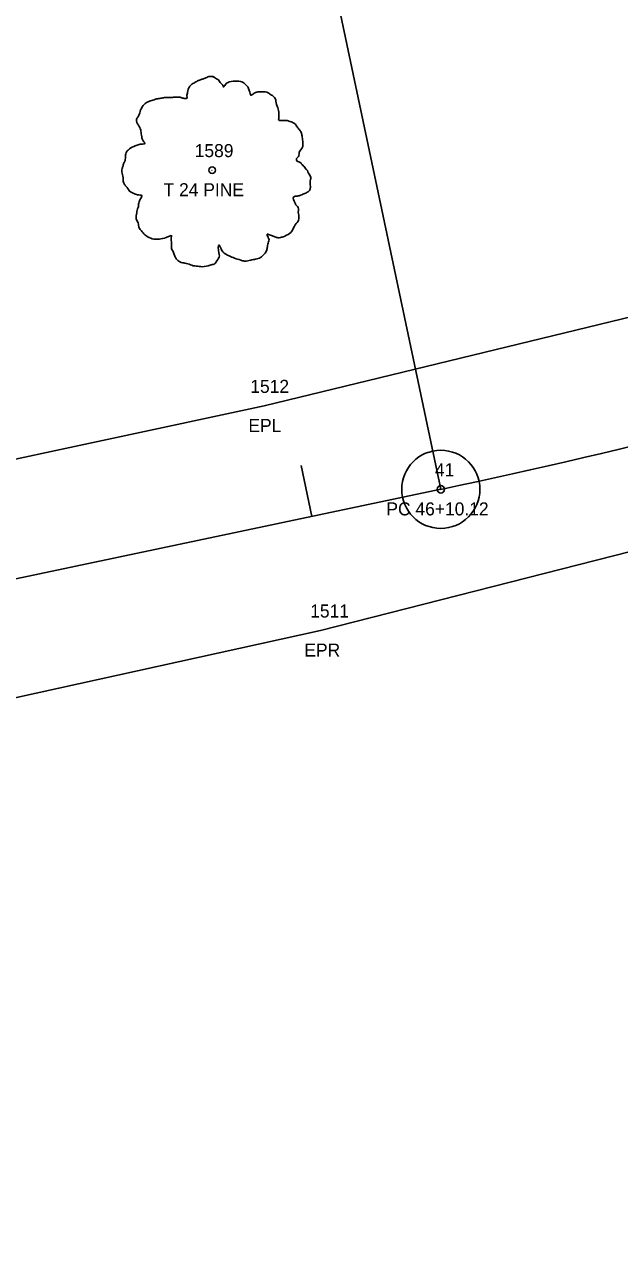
# Model space of a CAD drawing. Extents: x 1965304 to 1970247, y 1117014 to 1118201.
# Drawn here: x 1966652.9 to 1966698.6, y 1117363.8 to 1117457.6 of the extents above; entities that cross this region are included whole.
import ezdxf

# ---------------------------------------------------------------- set-up
doc = ezdxf.new("R2010")
doc.units = 0
for name, color, linetype in [('RD_EX_Road', 7, 'Continuous'), ('RD_EX_Road_txCode', 7, 'Continuous'), ('RD_EX_VEG', 7, 'Continuous'), ('RD_EX_VEG_txCode', 7, 'Continuous'), ('RD_HC_Cl', 7, 'Continuous'), ('RD_HC_Data', 7, 'Continuous'), ('RD_HC_Data_Tic', 7, 'Continuous'), ('RD_HC_txCode', 7, 'Continuous'), ('RD_SMD_Locator', 7, 'Continuous')]:
    doc.layers.add(name, color=color, linetype=linetype)

msp = doc.modelspace()

# ---------------------------------------------------------------- linework, layer by layer
at = {"layer": 'RD_EX_Road'}
for points in [[(1966031.823, 1117232.956), (1966074.66, 1117252.15), (1966117.782, 1117271.581), (1966161.06, 1117290.483), (1966205.406, 1117309.226), (1966251.249, 1117327.393), (1966297.245, 1117343.102), (1966344.085, 1117357.038), (1966390.785, 1117368.561), (1966438.122, 1117379.082), (1966484.547, 1117389.131), (1966531.199, 1117398.733), (1966578.388, 1117408.593), (1966604.527, 1117414.058), (1966624.537, 1117418.323), (1966671.319, 1117428.348), (1966716.506, 1117439.32), (1966736.604, 1117445.59), (1966754.133, 1117451.442), (1966759.658, 1117453.517), (1966769.512, 1117457.475)], [(1965729.992, 1117080.297), (1965819.77, 1117119.134), (1965907.737, 1117159.312), (1965995.365, 1117199.039), (1966039.268, 1117218.497), (1966081.241, 1117237.148), (1966124.666, 1117256.555), (1966167.659, 1117275.555), (1966211.467, 1117293.627), (1966257.791, 1117311.581), (1966302.7, 1117327.207), (1966347.903, 1117339.982), (1966394.806, 1117351.637), (1966441.557, 1117361.865), (1966488.625, 1117372.057), (1966534.906, 1117381.34), (1966581.234, 1117390.947), (1966629.533, 1117400.947), (1966675.632, 1117411.107), (1966721.676, 1117422.847), (1966766.802, 1117438.972), (1966775.751, 1117440.571)]]:
    msp.add_lwpolyline(points, dxfattribs=at)
at = {"layer": 'RD_EX_VEG'}
for centre, radius in [((1966667.339, 1117446.441), 0.25), ((1966667.339, 1117446.441), 0.25), ((1966667.326, 1117446.422), 0.0001), ((1966667.326, 1117446.422), 0.0001)]:
    msp.add_circle(centre, radius, dxfattribs=at)
for points in [[(1966667.471, 1117453.608), (1966667.171, 1117453.633), (1966666.846, 1117453.533), (1966666.596, 1117453.433), (1966666.371, 1117453.358), (1966666.146, 1117453.258), (1966665.846, 1117453.083), (1966665.622, 1117452.883), (1966665.497, 1117452.634), (1966665.447, 1117452.409), (1966665.397, 1117452.134), (1966665.397, 1117451.959), (1966665.272, 1117451.934), (1966665.122, 1117451.959), (1966664.872, 1117452.034), (1966664.622, 1117452.034), (1966664.372, 1117452.034), (1966664.022, 1117452.009), (1966663.672, 1117452.009), (1966663.398, 1117451.959), (1966663.073, 1117451.909), (1966662.698, 1117451.784), (1966662.348, 1117451.659), (1966662.048, 1117451.409), (1966661.798, 1117450.934), (1966661.673, 1117450.584), (1966661.523, 1117450.335), (1966661.673, 1117449.885), (1966661.848, 1117449.535), (1966661.873, 1117449.335), (1966661.948, 1117448.91), (1966662.048, 1117448.685), (1966662.173, 1117448.485), (1966662.098, 1117448.46), (1966661.723, 1117448.41), (1966661.423, 1117448.31), (1966660.999, 1117448.086), (1966660.774, 1117447.861), (1966660.674, 1117447.536), (1966660.649, 1117447.186), (1966660.549, 1117446.986), (1966660.474, 1117446.711), (1966660.449, 1117446.636), (1966660.399, 1117446.311), (1966660.499, 1117445.861), (1966660.524, 1117445.512), (1966660.649, 1117445.287), (1966660.799, 1117445.112), (1966660.974, 1117444.862), (1966661.373, 1117444.637), (1966661.698, 1117444.537), (1966661.898, 1117444.512), (1966661.723, 1117444.012), (1966661.673, 1117443.662), (1966661.548, 1117443.263), (1966661.548, 1117443.188), (1966661.498, 1117442.713), (1966661.648, 1117442.388), (1966661.723, 1117442.013), (1966661.898, 1117441.788), (1966662.173, 1117441.488), (1966662.498, 1117441.264), (1966662.998, 1117441.139), (1966663.398, 1117441.164), (1966663.972, 1117441.338), (1966664.222, 1117441.413), (1966664.197, 1117441.239), (1966664.222, 1117440.864), (1966664.222, 1117440.439), (1966664.372, 1117440.114), (1966664.472, 1117439.839), (1966664.622, 1117439.589), (1966664.947, 1117439.364), (1966665.347, 1117439.289), (1966665.771, 1117439.139), (1966666.221, 1117439.064), (1966666.721, 1117439.039), (1966667.321, 1117439.189), (1966667.596, 1117439.314), (1966667.696, 1117439.489), (1966667.896, 1117439.864), (1966667.846, 1117440.089), (1966667.871, 1117440.689), (1966667.97, 1117440.514), (1966668.145, 1117440.164), (1966668.645, 1117439.864), (1966669.045, 1117439.689), (1966669.52, 1117439.539), (1966669.82, 1117439.464), (1966670.294, 1117439.539), (1966670.669, 1117439.614), (1966671.044, 1117439.739), (1966671.344, 1117440.014), (1966671.519, 1117440.289), (1966671.569, 1117440.564), (1966671.644, 1117440.939), (1966671.694, 1117441.114)], [(1966667.471, 1117453.608), (1966667.171, 1117453.633), (1966666.846, 1117453.533), (1966666.596, 1117453.433), (1966666.371, 1117453.358), (1966666.146, 1117453.258), (1966665.846, 1117453.083), (1966665.622, 1117452.883), (1966665.497, 1117452.634), (1966665.447, 1117452.409), (1966665.397, 1117452.134), (1966665.397, 1117451.959), (1966665.272, 1117451.934), (1966665.122, 1117451.959), (1966664.872, 1117452.034), (1966664.622, 1117452.034), (1966664.372, 1117452.034), (1966664.022, 1117452.009), (1966663.672, 1117452.009), (1966663.398, 1117451.959), (1966663.073, 1117451.909), (1966662.698, 1117451.784), (1966662.348, 1117451.659), (1966662.048, 1117451.409), (1966661.798, 1117450.934), (1966661.673, 1117450.584), (1966661.523, 1117450.335), (1966661.673, 1117449.885), (1966661.848, 1117449.535), (1966661.873, 1117449.335), (1966661.948, 1117448.91), (1966662.048, 1117448.685), (1966662.173, 1117448.485), (1966662.098, 1117448.46), (1966661.723, 1117448.41), (1966661.423, 1117448.31), (1966660.999, 1117448.086), (1966660.774, 1117447.861), (1966660.674, 1117447.536), (1966660.649, 1117447.186), (1966660.549, 1117446.986), (1966660.474, 1117446.711), (1966660.449, 1117446.636), (1966660.399, 1117446.311), (1966660.499, 1117445.861), (1966660.524, 1117445.512), (1966660.649, 1117445.287), (1966660.799, 1117445.112), (1966660.974, 1117444.862), (1966661.373, 1117444.637), (1966661.698, 1117444.537), (1966661.898, 1117444.512), (1966661.723, 1117444.012), (1966661.673, 1117443.662), (1966661.548, 1117443.263), (1966661.548, 1117443.188), (1966661.498, 1117442.713), (1966661.648, 1117442.388), (1966661.723, 1117442.013), (1966661.898, 1117441.788), (1966662.173, 1117441.488), (1966662.498, 1117441.264), (1966662.998, 1117441.139), (1966663.398, 1117441.164), (1966663.972, 1117441.338), (1966664.222, 1117441.413), (1966664.197, 1117441.239), (1966664.222, 1117440.864), (1966664.222, 1117440.439), (1966664.372, 1117440.114), (1966664.472, 1117439.839), (1966664.622, 1117439.589), (1966664.947, 1117439.364), (1966665.347, 1117439.289), (1966665.771, 1117439.139), (1966666.221, 1117439.064), (1966666.721, 1117439.039), (1966667.321, 1117439.189), (1966667.596, 1117439.314), (1966667.696, 1117439.489), (1966667.896, 1117439.864), (1966667.846, 1117440.089), (1966667.871, 1117440.689), (1966667.97, 1117440.514), (1966668.145, 1117440.164), (1966668.645, 1117439.864), (1966669.045, 1117439.689), (1966669.52, 1117439.539), (1966669.82, 1117439.464), (1966670.294, 1117439.539), (1966670.669, 1117439.614), (1966671.044, 1117439.739), (1966671.344, 1117440.014), (1966671.519, 1117440.289), (1966671.569, 1117440.564), (1966671.644, 1117440.939), (1966671.694, 1117441.114)], [(1966671.694, 1117441.114), (1966671.619, 1117441.289), (1966671.569, 1117441.538), (1966671.644, 1117441.513), (1966671.819, 1117441.463), (1966672.094, 1117441.338), (1966672.319, 1117441.264), (1966672.643, 1117441.289), (1966672.918, 1117441.388), (1966673.368, 1117441.663), (1966673.643, 1117442.138), (1966673.918, 1117442.538), (1966673.993, 1117442.863), (1966673.943, 1117443.088), (1966673.918, 1117443.587), (1966673.718, 1117443.837), (1966673.668, 1117443.962), (1966673.568, 1117444.362), (1966673.643, 1117444.412), (1966673.918, 1117444.462), (1966674.293, 1117444.587), (1966674.568, 1117444.712), (1966674.793, 1117444.887), (1966674.867, 1117445.112), (1966674.843, 1117445.512), (1966674.892, 1117445.911), (1966674.818, 1117446.061), (1966674.718, 1117446.211), (1966674.643, 1117446.411), (1966674.493, 1117446.561), (1966674.393, 1117446.711), (1966674.293, 1117446.811), (1966674.168, 1117446.961), (1966673.993, 1117447.086), (1966673.843, 1117447.136), (1966673.793, 1117447.286), (1966673.943, 1117447.486), (1966673.993, 1117447.586), (1966674.018, 1117447.811), (1966674.243, 1117448.16), (1966674.293, 1117448.56), (1966674.243, 1117448.985), (1966674.193, 1117449.26), (1966674.043, 1117449.535), (1966673.843, 1117449.785), (1966673.718, 1117449.96), (1966673.543, 1117450.085), (1966673.218, 1117450.21), (1966672.968, 1117450.26), (1966672.618, 1117450.26), (1966672.419, 1117450.31), (1966672.444, 1117450.36), (1966672.444, 1117450.509), (1966672.444, 1117450.784), (1966672.369, 1117451.234), (1966672.219, 1117451.734), (1966672.219, 1117451.759), (1966672.119, 1117452.009), (1966671.894, 1117452.209), (1966671.719, 1117452.309), (1966671.519, 1117452.434), (1966671.269, 1117452.459), (1966670.969, 1117452.459), (1966670.694, 1117452.409), (1966670.494, 1117452.309), (1966670.319, 1117452.184), (1966670.244, 1117452.334), (1966670.145, 1117452.634), (1966670.095, 1117452.783), (1966669.945, 1117452.958), (1966669.72, 1117453.158), (1966669.27, 1117453.283), (1966668.645, 1117453.208), (1966668.345, 1117453.008), (1966668.195, 1117452.833), (1966668.145, 1117452.958), (1966667.945, 1117453.158), (1966667.846, 1117453.333), (1966667.671, 1117453.458), (1966667.521, 1117453.558), (1966667.421, 1117453.608)], [(1966671.694, 1117441.114), (1966671.619, 1117441.289), (1966671.569, 1117441.538), (1966671.644, 1117441.513), (1966671.819, 1117441.463), (1966672.094, 1117441.338), (1966672.319, 1117441.264), (1966672.643, 1117441.289), (1966672.918, 1117441.388), (1966673.368, 1117441.663), (1966673.643, 1117442.138), (1966673.918, 1117442.538), (1966673.993, 1117442.863), (1966673.943, 1117443.088), (1966673.918, 1117443.587), (1966673.718, 1117443.837), (1966673.668, 1117443.962), (1966673.568, 1117444.362), (1966673.643, 1117444.412), (1966673.918, 1117444.462), (1966674.293, 1117444.587), (1966674.568, 1117444.712), (1966674.793, 1117444.887), (1966674.867, 1117445.112), (1966674.843, 1117445.512), (1966674.892, 1117445.911), (1966674.818, 1117446.061), (1966674.718, 1117446.211), (1966674.643, 1117446.411), (1966674.493, 1117446.561), (1966674.393, 1117446.711), (1966674.293, 1117446.811), (1966674.168, 1117446.961), (1966673.993, 1117447.086), (1966673.843, 1117447.136), (1966673.793, 1117447.286), (1966673.943, 1117447.486), (1966673.993, 1117447.586), (1966674.018, 1117447.811), (1966674.243, 1117448.16), (1966674.293, 1117448.56), (1966674.243, 1117448.985), (1966674.193, 1117449.26), (1966674.043, 1117449.535), (1966673.843, 1117449.785), (1966673.718, 1117449.96), (1966673.543, 1117450.085), (1966673.218, 1117450.21), (1966672.968, 1117450.26), (1966672.618, 1117450.26), (1966672.419, 1117450.31), (1966672.444, 1117450.36), (1966672.444, 1117450.509), (1966672.444, 1117450.784), (1966672.369, 1117451.234), (1966672.219, 1117451.734), (1966672.219, 1117451.759), (1966672.119, 1117452.009), (1966671.894, 1117452.209), (1966671.719, 1117452.309), (1966671.519, 1117452.434), (1966671.269, 1117452.459), (1966670.969, 1117452.459), (1966670.694, 1117452.409), (1966670.494, 1117452.309), (1966670.319, 1117452.184), (1966670.244, 1117452.334), (1966670.145, 1117452.634), (1966670.095, 1117452.783), (1966669.945, 1117452.958), (1966669.72, 1117453.158), (1966669.27, 1117453.283), (1966668.645, 1117453.208), (1966668.345, 1117453.008), (1966668.195, 1117452.833), (1966668.145, 1117452.958), (1966667.945, 1117453.158), (1966667.846, 1117453.333), (1966667.671, 1117453.458), (1966667.521, 1117453.558), (1966667.421, 1117453.608)]]:
    msp.add_spline(points, degree=3, dxfattribs=at)
at = {"layer": 'RD_HC_Cl'}
msp.add_line((1966425.261, 1117367.215), (1966684.871, 1117421.945), dxfattribs=at)
msp.add_arc((1966579.594, 1117921.318), 510.35, 281.90472, 291.99584, dxfattribs=at)
at = {"layer": 'RD_HC_Data'}
msp.add_line((1966684.871, 1117421.945), (1966660.825, 1117536.006), dxfattribs=at)
for radius in [3, 3, 0.282, 0.282]:
    msp.add_circle((1966684.871, 1117421.945), radius, dxfattribs=at)
at = {"layer": 'RD_HC_Data_Tic'}
msp.add_line((1966674.973, 1117419.859), (1966674.148, 1117423.773), dxfattribs=at)
at = {"layer": 'RD_SMD_Locator'}
for centre in [(1966671.319, 1117428.348), (1966671.319, 1117428.348), (1966684.871, 1117421.945), (1966684.871, 1117421.945), (1966675.632, 1117411.107), (1966675.632, 1117411.107)]:
    msp.add_circle(centre, 0.001, dxfattribs=at)

# ---------------------------------------------------------------- texts
at = {"layer": 'RD_EX_Road_txCode'}
for s, p in [('1512', (1966670.256, 1117429.348)), ('1512', (1966670.256, 1117429.348)), ('EPL', (1966670.114, 1117426.348)), ('EPL', (1966670.114, 1117426.348)), ('1511', (1966674.853, 1117412.107)), ('1511', (1966674.853, 1117412.107)), ('EPR', (1966674.404, 1117409.107)), ('EPR', (1966674.404, 1117409.107))]:
    msp.add_text(s, height=1, dxfattribs=at).set_placement(p)
at = {"layer": 'RD_EX_VEG_txCode'}
for s, p in [('1589', (1966665.992, 1117447.441)), ('1589', (1966665.992, 1117447.441)), ('T 24 PINE', (1966663.603, 1117444.441)), ('T 24 PINE', (1966663.603, 1117444.441))]:
    msp.add_text(s, height=1, dxfattribs=at).set_placement(p)
at = {"layer": 'RD_HC_txCode'}
for s, p in [('41', (1966684.423, 1117422.945)), ('41', (1966684.423, 1117422.945)), ('PC 46+10.12', (1966680.698, 1117419.945)), ('PC 46+10.12', (1966680.698, 1117419.945))]:
    msp.add_text(s, height=1, dxfattribs=at).set_placement(p)

doc.saveas('drawing.dxf')
